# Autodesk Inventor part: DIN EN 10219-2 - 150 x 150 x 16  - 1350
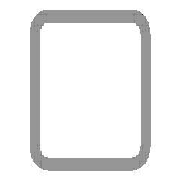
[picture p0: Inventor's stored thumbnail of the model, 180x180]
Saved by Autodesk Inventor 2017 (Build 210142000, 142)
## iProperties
Created: 2017-11
Part Number: DIN EN 10219-2 - 150 x 150 x 16  - 1350
Material: Steel, Mild
Description: Cold formed welded structural hollow sections of non-alloy and fine grain structural steel
Document SubType Name: Modeling
Standard: DIN
Designer: iusti
Standard Revision: 2006-07
Standards Organization: DIN
Language: en-US
Size Designation: 150 x 150 x 16
Categories: <MemberInstance><Categories><Category DisplayName="Structural Shapes" InternalName="089c4875-fa83-4c05-b084-43b9cc11f5ed" Mnemonic="GRDR"><CategoryParameter Dis
Stock Number: 150 x 150 x 16
Mass: 79240 g
Surface Area: 12767.4 cm^2
Volume: 10094.3 cm^3
Density: 7.85 g/cm^3
Appearance: Semi-Polished
_CCFamilyMember: 76
_CCFamilyDisplayName: DIN EN 10219-2 (Square Hollow Section - Cold Formed) - Cold formed welded structural hollow sections of non-alloy and fine grain structural steel
_FrameMemberDoc: Frame Member File
_Version: 15.0.0
_GetPNFromCC: 1
IsCustomPart: 1
G_L: 1350.000 mm
G_W: 150.000 mm
G_H: 150.000 mm
+256F9982-8F43-4545-88E3-061E3400206B+CUTDETAIL1: Cut
+92690F86-3DA3-4326-AD70-C27C8C39E2A5+CUTDETAIL2: Cut
Author: iusti
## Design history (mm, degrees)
node "Start plane"
node "End plane"
sketch "Sketch"
  geometry: L1 (-75, -27)-(-75, 27); L2 (-27, 75)-(27, 75); L3 (75, 27)-(75, -27); L4 (27, -75)-(-27, -75); L5 (-27, 59)-(27, 59); L6 (59, 27)-(59, -27); L7 (27, -59)-(-27, -59); L8 (-59, -27)-(-59, 27); L9 (0, 118.918)-(0, -118.918) reference; L10 (-118.918, 0)-(118.918, 0) reference; A1 r 48 centre (-27, -27) between (-75, -27) and (-27, -75); A2 r 48 centre (-27, 27) between (-27, 75) and (-75, 27); A3 r 48 centre (27, 27) between (75, 27) and (27, 75); A4 r 48 centre (27, -27) between (27, -75) and (75, -27); A5 r 32 centre (-27, 27) between (-27, 59) and (-59, 27); A6 r 32 centre (27, 27) between (59, 27) and (27, 59); A7 r 32 centre (27, -27) between (27, -59) and (59, -27); A8 r 32 centre (-27, -27) between (-59, -27) and (-27, -59)
  constraints: 16 end point, 16 point on circle, 8 centre point, 8 tangent, 4 parallel, 3 equal radius, 2 perpendicular, 7 other
  dimensions: "d7" = 48 radius of A1 (= G_IR); "d10" = 150 distance between parallel lines of L2 L4 (= G_H); "d11" = 150 distance between parallel lines of L1 L3 (= G_W); "d12" = 16 distance between parallel lines of L3 L6 (= G_T); "d15" = 75 distance between parallel lines of L2 L10 (= 0.5 x d10); "d16" = 75 distance between parallel lines of L9 L3 (= 0.5 x d11)
extrude "Body" new body sketch "Sketch" stored distance "d3" = 1350 (= G_L); taper "d4" = 0 deg
node "Driven Length"
  sketch "Sketch3"
    geometry: L1 (0, 0)-(10, 0) reference
    constraints: 2 end point, 1 horizontal
  workplane "Work Plane3"
  sketch "Sketch4"
    geometry: L1 (-2, 75)-(12, 75) reference; L2 (-2, 1425)-(12, 1425) reference
    dimensions: "d18" = 1350 distance between parallel lines of L1 L2 (derived)
workplane "Work Plane4"
split "Split1"
workplane "Work Plane5"
split "Split2"
body "Solid1"
other parameters: "G_W" = 150 [user parameter; used in 1 equation term], "G_H" = 150 [user parameter; used in 1 equation term], "G_T" = 16 [user parameter; used in 1 equation term], "G_IR" = 48 [user parameter; used in 1 equation term], "G_L" = 1350 (= d18) [user parameter; used in 1 equation term], "G_OFFSET_START" = -75 [user parameter; used in 1 equation term], "G_OFFSET_END" = -75 [user parameter; used in 1 equation term], "d13" = 75 (= -G_OFFSET_START), "d14" = 1425 (= G_OFFSET_END + B_L), "d17" = 90 deg
